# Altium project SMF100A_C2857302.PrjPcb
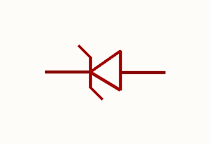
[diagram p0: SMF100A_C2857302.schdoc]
1 sheet, 1 parts. Net scope: global (net labels, ports and power ports of the same name join across sheets).

## Sheet SMF100A_C2857302.schdoc
size 127 x 101 mm

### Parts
D?  smf100a_c2857302  [SOD-123FL_L2.8-W1.9-LS3.7-RD]  (value not drawn)

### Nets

Not connected (* = marked no-connect by the designer): D? 1(C) 2(A)

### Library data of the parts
D? = smf100a_c2857302: 极性:单向;反向截止电压(Vrwm):100V;钳位电压:162V;峰值脉冲电流(Ipp):1.2A;峰值脉冲功率(Ppp):200W@10/1000us;击穿电压(VBR):111V;; Manufacturer: JSMSEMI(杰盛微); AddInBom: yes; ModelId: ee80cc4b5e2f4a0b8a944bbfc66c96ba; ModelTransform: 141.732,74.803,0,0,0,0,0,0,0; Polarity: 单向; Reverse Stand-Off Voltage (Vrwm): 100V; Clamping Voltage: 162V; Peak Pulse Current (Ipp): 1.2A; Voltage - Breakdown: 111V; Reverse Leakage Current (Ir): 1uA; Number of Channels: 单路; Type: TVS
